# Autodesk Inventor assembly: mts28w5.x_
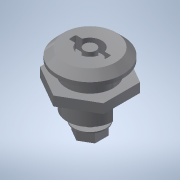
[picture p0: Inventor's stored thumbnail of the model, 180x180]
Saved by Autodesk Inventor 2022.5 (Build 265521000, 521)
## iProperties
Part Number: mts28w5.x_
Material: 一般
Document SubType Name: Assembly
Designer: ImaoCorp
Sending System: SOLIDWORKS 2017-2017317
MC: AMD64
MC_MODEL: Intel64 Family 6 Model 60 Stepping 3, GenuineIntel
OS: Windows_NT
FRU: Parasolid Version 29.0, build 201,  4-17-2017
FORMAT: text
GUISE: transmit
KEY: mts28w5
FILE: mts28w5.x_t
DATE: Fri Jul 26 11:49:30 2019
Author: ImaoCorp
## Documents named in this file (4)
- X:\14_SW2022-Inv2022\00_全2023-1023新製品(TCC)まで\m\mts28w5\MTS28W5.iam
- X:\14_SW2022-Inv2022\00_全2023-1023新製品(TCC)まで\m\mts28w5\mts28w5_01.ipt
- X:\14_SW2022-Inv2022\00_全2023-1023新製品(TCC)まで\m\mts28w5\mts28w5_02.ipt
- X:\14_SW2022-Inv2022\00_全2023-1023新製品(TCC)まで\m\mts28w5\mts28w5_03.ipt
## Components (3 placed, 3 different names)
1. mts28w5_01
2. mts28w5_02
3. mts28w5_03
